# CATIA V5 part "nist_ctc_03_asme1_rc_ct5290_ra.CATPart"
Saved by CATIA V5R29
Part number: NIST Test Case 3 CATIA V5R29 RB
Revision: B
Nomenclature: Test Case 3 Baseline
Property "Modeled By": "Rich Eckenrode, RECON Services.com - Revised by DS"
Property "CAGE Code": "64JW1"
Property "Company": "RECON Services Incorporated"
Bounding box of the stored display mesh (mm): x -249.558 to 53.402, y 0 to 485.445, z 0 to 162.69
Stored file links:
  E:\users\dgn\TPS V5\Import-export annotations\Step\PMI representation 2015\NIST UC\CTC\nist_ctc_03_asme1_ct5210_rc - V5R29.CATPart
  E:\users\dgn\TPS V5\Import-export annotations\Step\PMI representation 2015\NIST UC\CTC\nist_ctc_03_asme1_ct5210_rc.CATPart
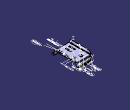
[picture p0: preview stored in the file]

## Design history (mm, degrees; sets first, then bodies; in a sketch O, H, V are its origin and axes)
TTRSSet1
AxisSystem1: origin (-19.05, 466.3948, 0), X (0, 1, 0), Y (-1, 0, 0), Z (0, 0, 1)
AxisSystem2: origin (-19.05, 466.3948, 78.105), X (0, 1, 0), Y (-1, 0, 0), Z (0, 0, 1)
AxisSystem3: origin (30.5008, 244.6249, 141.1371), X (0, 1, 0), Y (-0.7071, 0, -0.7071), Z (-0.7071, 0, 0.7071)
f4a2d38f3ddc11d3a929006094b99c4b_11 "CATTPSSet"
Body1 (main body)
  Sketch1 on yz-plane, origin (0, 0, 0), H (0, 1, 0), V (0, 0, 1)
    line L1 (49.8297, 8.2575) -> (49.8297, 69.85)
    line L2 (58.0873, 78.1075) -> (426.3873, 78.1075)
    point P1 (434.6448, 78.1075)
    line L3 (434.6448, 69.85) -> (434.6448, 8.2575)
    point P2 (434.6448, 1.9075)
    line L4 (43.4797, 1.9075) -> (0, 1.9075)
    point P3 (0, 1.9075)
    line L5 (440.9948, 1.9075) -> (485.4448, 1.9075)
    point P4 (485.4448, 1.9075)
    arc A1 centre (440.9948, 8.2575) radius 6.35 from (440.9948, 1.9075) to (434.6448, 8.2575) cw
    arc A2 centre (43.4797, 8.2575) radius 6.35 from (43.4797, 1.9075) to (49.8297, 8.2575) ccw
    arc A3 centre (426.3873, 69.85) radius 8.2575 from (434.6448, 69.85) to (426.3873, 78.1075) ccw
    arc A4 centre (58.0873, 69.85) radius 8.2575 from (58.0873, 78.1075) to (49.8297, 69.85) ccw
    line L6 (440.9948, 0) -> (485.4448, 0)
    arc A5 centre (440.9948, 8.2575) radius 8.2575 from (432.7373, 8.2575) to (440.9948, 0) ccw
    line L7 (432.7373, 69.85) -> (432.7373, 8.2575)
    arc A6 centre (426.3873, 69.85) radius 6.35 from (432.7373, 69.85) to (426.3873, 76.2) ccw
    line L8 (58.0873, 76.2) -> (426.3873, 76.2)
    arc A7 centre (58.0873, 69.85) radius 6.35 from (58.0873, 76.2) to (51.7373, 69.85) ccw
    line L9 (51.7373, 8.2575) -> (51.7373, 69.85)
    arc A8 centre (43.4797, 8.2575) radius 8.2575 from (43.4797, 0) to (51.7373, 8.2575) ccw
    line L10 (43.4797, 0) -> (0, 0)
    line L11 (0, 0) -> (0, 1.9075)
    line L12 (485.4448, 0) -> (485.4448, 1.9075)
    distance P2 P4 = 50.8
    distance P1 P2 = 76.2
    radius A1 = 6.35
    radius A2 = 6.35
    radius A3 = 8.2575
    radius A4 = 8.2575
    distance L6 L5 = 1.9075
    distance L3 L7 = 1.9075
    distance L2 L8 = 1.9075
    distance L9 L1 = 1.9075
    distance L10 L4 = 1.9075
    distance H L10 = 0
    distance V L12 = 485.4448
    radius A6 = 6.35
    radius A5 = 8.2575
    radius A7 = 6.35
    radius A8 = 8.2575
    distance L7 L9 = 381
    vertical: L1 V, L3 V, L11 V, L12 V
    horizontal: L2 H, L4 H, L5 H
    coincidence: P3 V, L4 L5, L5 P2, L3 P2, L3 P1, L2 P1
    tangency: A1 L5, A1 L3, A2 L4, A2 L1, A3 L3, A3 L2, A4 L2, A4 L1, L10 A8, A8 L9, A7 L8, A7 L9, A5 L7, L6 A5, L7 A6, A6 L8
  Pad1: profile Sketch1, direction (-1, 0, 0), length 241.3
  Plane1: type Offset, RefPlane zx-plane, Offset 426.3873
  Sketch2 on Plane1, origin (0, 426.3873, 0), H (-1, 0, 0), V (0, 0, 1)
    line L1 (247.65, 128.9075) -> (249.5575, 128.9075)
    line L2 (249.5575, 128.9075) -> (249.5575, 84.4575)
    line L3 (247.65, 84.4575) -> (247.65, 128.9075)
    line L4 (-6.35, 116.2075) -> (-8.2575, 116.2075)
    line L5 (-8.2575, 116.2075) -> (-8.2575, 84.4575)
    line L6 (-6.35, 84.4575) -> (-6.35, 116.2075)
    point P5 (-6.35, 84.4575)
    projected line E1 (0, 78.1075) -> (241.3, 78.1075) from edge [face of Pad1 from Sketch1.A3 | face of Pad1 from Sketch1.L2]
    point P7 (241.3, 78.1075)
    projected line E2 (241.3, 69.85) -> (241.3, 78.1075) from edge [end face of Pad1 | face of Pad1 from Sketch1.A3]
    projected line E3 (241.3, 76.2) -> (241.3, 78.1075) from edge [end face of Pad1 | face of Pad1 from Sketch1.A3]
    arc A1 centre (241.3, 84.4575) radius 6.35 from (241.3, 78.1075) to (247.65, 84.4575) ccw
    point P11 (241.3, 78.1075)
    arc A2 centre (241.3, 84.4575) radius 8.2575 from (241.3, 76.2) to (249.5575, 84.4575) ccw
    projected line E4 (0, 69.85) -> (0, 78.1075) from edge [face of Pad1 from Sketch1.A3 | start face of Pad1]
    projected line E5 (0, 76.2) -> (0, 78.1075) from edge [face of Pad1 from Sketch1.A3 | start face of Pad1]
    point P17 (0, 78.1075)
    arc A3 centre (0, 84.4575) radius 6.35 from (0, 78.1075) to (-6.35, 84.4575) cw
    point P18 (0, 84.4575)
    arc A4 centre (0, 84.4575) radius 8.2575 from (-8.2575, 84.4575) to (0, 76.2) ccw
    point P19 (-8.2575, 84.4575)
    point P20 (0, 76.2)
    construction line L7 (-6.35, 84.4575) -> (-8.2575, 84.4575)
    construction line L8 (0, 78.1075) -> (0, 76.2)
    distance L3 L2 = 1.9075
    distance E1 L1 = 50.8
    radius A1 = 6.35
    radius A2 = 8.2575
    distance A1 A2 = 1.9075
    radius A3 = 6.35
    distance A3 A4 = 1.9075
    distance E1 L4 = 38.1
    horizontal: L1 H, L4 H
    vertical: L2 V, L3 V, L5 V, L6 V
    tangency: A1 E1, A1 L3, A2 L2, A3 E1, A3 L6, A4 L5
    coincidence: P11 P7, L7 P18, L8 P18, P20 A4, P17 A3, P19 A4, P5 A3, P5 L6
    concentricity: A3 A4
  Pad2: profile Sketch2, direction (0, -1, 0), length 368.3
  Sketch3 on face of Pad2 from Sketch2.L5, origin (8.2575, 0, 0), H (0, 1, 0), V (0, 0, 1)
    line L1 (81.9434, 136.649) -> (117.6249, 100.9675)
    line L2 (117.6249, 100.9675) -> (371.6249, 100.9675)
    point P3 (371.6249, 100.9675)
    line L3 (371.6249, 100.9675) -> (407.3063, 136.649)
    line L4 (407.3063, 136.649) -> (81.9434, 136.649)
    reference projected line E1 (426.3873, 116.2075) -> (58.0873, 116.2075) from edge [face of Pad2 from Sketch2.L4 | face of Pad2 from Sketch2.L5]
    reference projected line E2 (426.3873, 116.2075) -> (426.3873, 84.4575) from edge [face of Pad2 from Sketch2.L5 | start face of Pad2]
    angle L3 L2 = 135
    angle L2 L1 = 135
    distance E1 L2 = 15.24
    length L2 = 254
    distance E2 P3 = 54.7624
    horizontal: L2 H, L4 H
  Pocket1: profile Sketch3, direction (-1, 0, 0), length 25.4
  Plane2: type Offset, RefPlane zx-plane, Offset 308.1249
  Sketch4 on Plane2, origin (0, 308.1249, 0), H (-1, 0, 0), V (0, 0, 1)
    projected line E1 (-8.2575, 100.9675) -> (-6.35, 100.9675) from edge [face of Pocket1 from Sketch3.L2 | face of Pocket1 from Sketch3.L1]
    line L1 (-6.35, 100.9675) -> (-6.35, 113.5659)
    line L2 (-8.2575, 100.9675) -> (-8.2575, 113.5659)
    line L3 (-8.7686, 119.4049) -> (-52.0534, 162.6897)
    line L4 (-10.1174, 118.0561) -> (-53.4022, 161.3409)
    line L5 (-53.4022, 161.3409) -> (-52.0534, 162.6897)
    arc A1 centre (-14.6075, 113.5659) radius 6.35 from (-8.2575, 113.5659) to (-10.1174, 118.0561) ccw
    arc A2 centre (-14.6075, 113.5659) radius 8.2575 from (-6.35, 113.5659) to (-8.7686, 119.4049) ccw
    point P9 (-14.6075, 113.5659)
    reference projected line E2 (0, 78.1075) -> (241.3, 78.1075) from edge [face of Pad1 from Sketch1.A3 | face of Pad1 from Sketch1.L2]
    radius A1 = 6.35
    distance L3 L4 = 1.9075
    distance E2 P9 = 35.4584
    angle L2 L4 = 45
    distance P9 L5 = 61.214
    distance L2 P9 = 6.35
    vertical: L1 V, L2 V
    perpendicularity: L5 L3
    tangency: A1 L2, A1 L4, A2 L1, A2 L3
  Pad3: profile Sketch4, direction (0, -1, 0), length 127
  Sketch5 on face of Pad1 from Sketch1.L5, origin (0, 0, 1.9075), H (1, 0, 0), V (0, 1, 0)
    line L1 (-184.15, 520.3001) -> (-57.15, 520.3001)
    line L2 (-57.15, 520.3001) -> (-57.15, 460.0448)
    line L3 (-63.5, 453.6948) -> (-177.8, 453.6948)
    line L4 (-184.15, 460.0448) -> (-184.15, 520.3001)
    point P3 (-184.15, -13.2588)
    line L5 (-184.15, -13.2588) -> (-57.15, -13.2588)
    line L6 (-57.15, -13.2588) -> (-57.15, 25.4)
    line L7 (-63.5, 31.75) -> (-177.8, 31.75)
    line L8 (-184.15, 25.4) -> (-184.15, -13.2588)
    point P5 (-57.15, 31.75)
    arc A1 centre (-177.8, 25.4) radius 6.35 from (-184.15, 25.4) to (-177.8, 31.75) cw
    arc A2 centre (-63.5, 25.4) radius 6.35 from (-63.5, 31.75) to (-57.15, 25.4) cw
    arc A3 centre (-63.5, 460.0448) radius 6.35 from (-63.5, 453.6948) to (-57.15, 460.0448) ccw
    arc A4 centre (-177.8, 460.0448) radius 6.35 from (-177.8, 453.6948) to (-184.15, 460.0448) cw
    length L5 = 127
    distance H L7 = 31.75
    distance L7 L3 = 421.9448
    distance V L6 = 57.15
    radius A1 = 6.35
    radius A2 = 6.35
    radius A3 = 6.35
    radius A4 = 6.35
    horizontal: L1 H, L3 H, L5 H, L7 H
    vertical: L2 V, L4 V, L6 V, L8 V
    coincidence: P3 L4, P5 L2, L2 L6, L8 L4, L7 P5, L6 P5
    tangency: A1 L8, A1 L7, A2 L7, A2 L6, A3 L3, A3 L2, A4 L3, A4 L4
  Pocket2: profile Sketch5, direction (0, 0, -1), length 127
  Sketch6 on face of Pad1 from Sketch1.L4, origin (-23.0976, 19.7224, 1.9075), H (1, 0, 0), V (0, 1, 0)
    point P1 (4.0476, -0.6724)
    distance P1 = 19.05
    distance P1 = 19.05
  Hole1: placed by Sketch6, at (-19.05, 19.05, 1.9075) direction (0, 0, -1), diameter 11.1252, through (limit type 3)
  RectPattern1: of Hole1, direction 1 instances 2, spacing 447.3448, along edge [face of Pad1 from Sketch1.L4 | start face of Pad1] reversed, direction 2 instances 2, spacing 203.2, along edge [face of Pad1 from Sketch1.L4 | face of Pad1 from Sketch1.L11]
  Sketch7 on face of Pad1 from Sketch1.L2, origin (0, 0, 78.1075), H (1, 0, 0), V (0, 1, 0)
    circle A1 centre (-63.0174, 331.5208) radius 19.05
    point P1 (-63.0174, 331.5208)
    circle A2 centre (-151.9174, 356.9208) radius 25.4
    point P2 (-151.9174, 356.9208)
    arc A3 centre (-126.5174, 122.0724) radius 9.525 from (-136.0424, 122.0724) to (-116.9924, 122.0724) ccw
    arc A4 centre (-126.5174, 210.9724) radius 9.525 from (-116.9924, 210.9724) to (-136.0424, 210.9724) ccw
    point P4 (-126.5174, 210.9724)
    arc A5 centre (-190.0174, 210.9724) radius 9.525 from (-180.4924, 210.9724) to (-199.5424, 210.9724) ccw
    point P5 (-190.0174, 210.9724)
    arc A6 centre (-190.0174, 122.0724) radius 9.525 from (-199.5424, 122.0724) to (-180.4924, 122.0724) ccw
    point P6 (-190.0174, 122.0724)
    line L1 (-199.5424, 210.9724) -> (-199.5424, 122.0724)
    line L2 (-180.4924, 210.9724) -> (-180.4924, 122.0724)
    line L3 (-136.0424, 210.9724) -> (-136.0424, 122.0724)
    line L4 (-116.9924, 210.9724) -> (-116.9924, 122.0724)
    construction line L5 (-126.5174, 122.0724) -> (-126.5174, 208.6119)
    axis line L6 (-324.5051, 166.5224) -> (-91.1048, 166.5224)
    radius A3 = 9.525
    radius A6 = 9.525
    radius A2 = 25.4
    radius A1 = 19.05
    distance A4 A3 = 107.95
    distance A5 A6 = 107.95
    distance P4 P5 H = 63.5
    distance P5 P4 V = 0
    distance V L5 = 126.5174
    distance H L6 = 166.5224
    distance P6 L6 = 44.45
    distance L5 P2 = 25.4
    distance P2 P1 H = 88.9
    distance P1 P2 V = 25.4
    distance H P1 = 331.5208
    tangency: L1 A6, L2 A5, L4 A4, A3 L3, A3 L4, A4 L3, A5 L1, L2 A6
    vertical: L1 V, L3 V, L4 V, L2 V, L5 V
    horizontal: L6 H
  Pocket3: profile Sketch7, direction (0, 0, -1), length 127
  Sketch8 on face of Pad1 from Sketch1.L2, origin (-36.0464, 89.7997, 78.1075), H (1, 0, 0), V (0, 1, 0)
    point P1 (-2.0536, 6.9743)
    reference intersected line E1 through (36.0464, 0) direction (0, 1) from yz-plane
    reference intersected line E2 through (0, -89.7997) direction (-1, 0) from zx-plane
    distance E1 P1 = 38.1
    distance E2 P1 = 96.774
  Hole2: placed by Sketch8, at (-38.1, 96.774, 78.1075) direction (0, 0, -1), diameter 15.875, through (limit type 3)
  RectPattern2: of Hole2, direction 1 instances 4, spacing 44.45, along edge [face of Pad1 from Sketch1.L4 | start face of Pad1] reversed, direction 2 instances 2, spacing 203.2
  Sketch9 on face of Pad3 from Sketch4.L3, origin (-55.3182, 0, 55.3182), H (0, -1, 0), V (0.7071, 0, 0.7071)
    circle A1 centre (-244.6249, 121.3663) radius 13.5255
    point P1 (-244.6249, 121.3663)
    reference projected line E1 (-181.1249, 90.6323) -> (-181.1249, 151.8463) from edge [end face of Pad3 | face of Pad3 from Sketch4.L3]
    reference projected line E2 (-308.1249, 151.8463) -> (-181.1249, 151.8463) from edge [face of Pad3 from Sketch4.L3 | face of Pad3 from Sketch4.L5]
    radius A1 = 13.5255
    distance E1 P1 = 63.5
    distance E2 P1 = 30.48
  Pocket4: profile Sketch9, direction (0.7071, 0, -0.7071), length 127
  Sketch10 on face of Pad3 from Sketch4.L3, origin (39.2454, 225.5348, 149.8817), H (0.7071, 0, 0.7071), V (0, 1, 0)
    point P1 (5.4133, 0.0401)
    reference projected line E1 (18.1133, 82.5901) -> (18.1133, -44.4099) from edge [face of Pad3 from Sketch4.L3 | face of Pad3 from Sketch4.L5]
    reference projected line E2 (-43.1007, -44.4099) -> (18.1133, -44.4099) from edge [end face of Pad3 | face of Pad3 from Sketch4.L3]
    distance E1 P1 = 12.7
    distance E2 P1 = 44.45
  Hole3: placed by Sketch10, at (43.0732, 225.5749, 153.7095) direction (0.7071, 0, -0.7071), diameter 4.7625, through (limit type 3)
  RectPattern3: of Hole3, direction 1 instances 2, spacing 38.1, along edge [face of Pad3 from Sketch4.L3 | face of Pad3 from Sketch4.L5] reversed, direction 2 instances 2, spacing 31.75, along edge [face of Pad3 from Sketch4.L3 | start face of Pad3] reversed
  Sketch11 on face of Pad1 from Sketch1.L2, origin (0, 0, 78.1075), H (1, 0, 0), V (0, 1, 0)
    point P1 (-8.89, 59.9897)
    line L1 (-8.89, 59.9897) -> (24.8074, 59.9897)
    line L2 (24.8074, 59.9897) -> (24.8074, 49.8297)
    line L3 (24.8074, 49.8297) -> (-8.89, 49.8297)
    line L4 (-8.89, 49.8297) -> (-8.89, 59.9897)
    point P2 (24.8074, 59.9897)
    point P3 (24.8074, 49.8297)
    point P4 (-8.89, 49.8297)
    reference projected line E1 (0, 49.8297) -> (-241.3, 49.8297) from edge [face of Pad1 from Sketch1.A4 | face of Pad1 from Sketch1.L1]
    construction line L5 (108.0077, 242.7224) -> (-387.5024, 242.7224)
    axis line L6 (-120.65, 508.962) -> (-120.65, -24.335)
    reference projected line E2 (0, 485.4448) -> (0, 440.9948) from edge [face of Pad1 from Sketch1.L5 | start face of Pad1]
    reference projected line E3 (-241.3, 485.4448) -> (-241.3, 440.9948) from edge [end face of Pad1 | face of Pad1 from Sketch1.L5]
    point P9 (-8.89, 425.4551)
    point P10 (24.8074, 425.4551)
    point P11 (24.8074, 435.6151)
    point P12 (-8.89, 435.6151)
    line L7 (-8.89, 425.4551) -> (24.8074, 425.4551)
    line L8 (24.8074, 425.4551) -> (24.8074, 435.6151)
    line L9 (24.8074, 435.6151) -> (-8.89, 435.6151)
    line L10 (-8.89, 435.6151) -> (-8.89, 425.4551)
    point P13 (-232.41, 59.9897)
    point P14 (-266.1074, 59.9897)
    point P15 (-266.1074, 49.8297)
    point P16 (-232.41, 49.8297)
    line L11 (-232.41, 59.9897) -> (-266.1074, 59.9897)
    line L12 (-266.1074, 59.9897) -> (-266.1074, 49.8297)
    line L13 (-266.1074, 49.8297) -> (-232.41, 49.8297)
    line L14 (-232.41, 49.8297) -> (-232.41, 59.9897)
    point P17 (-232.41, 425.4551)
    point P18 (-266.1074, 425.4551)
    point P19 (-266.1074, 435.6151)
    point P20 (-232.41, 435.6151)
    line L15 (-232.41, 425.4551) -> (-266.1074, 425.4551)
    line L16 (-266.1074, 425.4551) -> (-266.1074, 435.6151)
    line L17 (-266.1074, 435.6151) -> (-232.41, 435.6151)
    line L18 (-232.41, 435.6151) -> (-232.41, 425.4551)
    distance L1 L3 = 10.16
    distance V L4 = 8.89
    distance E1 L3 = 0
    distance V L6 = 120.65
    distance H L5 = 242.7224
    distance E2 E3 = 241.3 (reference)
    horizontal: L1 H, L3 H, L5 H
    vertical: L2 V, L4 V, L6 V
    symmetry: P1 P9 L5, P2 P10 L5, P3 P11 L5, P4 P12 L5, L1 L7 L5, L2 L8 L5, L3 L9 L5, L4 L10 L5, P1 P13 L6, P2 P14 L6, P3 P15 L6, P4 P16 L6, L1 L11 L6, L2 L12 L6, L3 L13 L6, L4 L14 L6, P9 P17 L6, P10 P18 L6, P11 P19 L6, P12 P20 L6, L7 L15 L6, L8 L16 L6, L9 L17 L6, L10 L18 L6
  Pocket5: profile Sketch11, direction (0, 0, -1), length 20.828, opposite side length 76.2
  Fillet1: radius 6.35, on edge [face of Pocket2 from Sketch5.L4 | face of Pad1 from Sketch1.L12]; edge [face of Pad1 from Sketch1.L12 | face of Pocket2 from Sketch5.L2]
  Chamfer1: length 12.7, angle 45, on edge [face of Pad1 from Sketch1.L12 | start face of Pad1]; edge [end face of Pad1 | face of Pad1 from Sketch1.L12]; edge [face of Pad1 from Sketch1.L11 | start face of Pad1]; edge [end face of Pad1 | face of Pad1 from Sketch1.L11]
  Chamfer2: length 25.4, angle 45, on edge [face of Pad2 from Sketch2.L1 | face of Pocket5 from Sketch11.L11]; edge [face of Pocket5 from Sketch11.L15 | face of Pad2 from Sketch2.L1]
  Fillet2: radius 12.7, on edge [face of Pad3 from Sketch4.L5 | start face of Pad3]; edge [end face of Pad3 | face of Pad3 from Sketch4.L5]
  Fillet3: radius 12.7, on edge [face of Pocket5 from Sketch11.L7 | face of Pad2 from Sketch2.L4]; edge [face of Pad2 from Sketch2.L4 | face of Pocket5 from Sketch11.L1]
  Point1: type Center, Curve edge [face of RectPattern1 | face of Pad1 from Sketch1.L5]
  Point2: type Center, Curve edge [face of Pad1 from Sketch1.L6 | face of RectPattern1]
  Point3: (0, 0, 78.105), relative to Point2
  Point4: type Center, Curve edge [face of Pad3 from Sketch4.L3 | face of Pocket4 from Sketch9.A1]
